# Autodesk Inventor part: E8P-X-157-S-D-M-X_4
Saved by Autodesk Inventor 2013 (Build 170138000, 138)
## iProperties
Created: 2012-07
Part Number: E8P-X-157-S-D-M-X_4
Material: Allgemein
Document SubType Name: Modeling
Designer: rYan
Density: 1 g/cm^3
Mass: 0.688704 g
Surface Area: 12.4844 cm^2
Volume: 0.688704 cm^3
Author: rYan
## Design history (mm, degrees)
node "E8P-X-157-S-D-M-X_41"
node "E8P-X-157-S-D-M-X_4"
node "Basis1"
